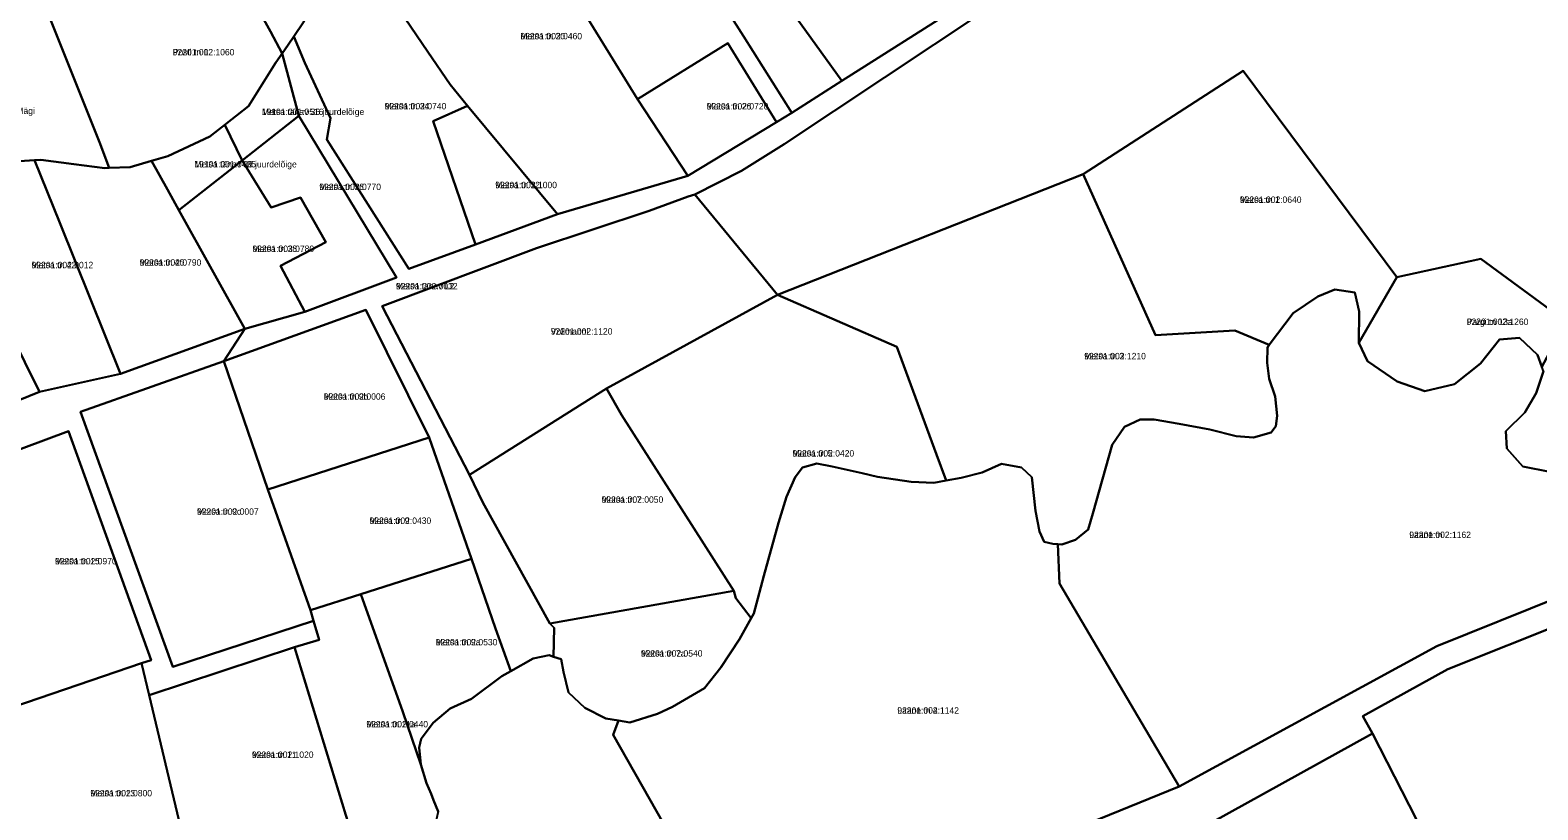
# Model space of a CAD drawing. Extents: x 601493 to 643081, y 6584980 to 6634019.
# Drawn here: x 610753.7 to 611108.4, y 6605638.6 to 6605821.9 of the extents above; entities that cross this region are included whole.
import ezdxf

# ---------------------------------------------------------------- set-up
doc = ezdxf.new("R2010")
doc.units = 0
for name, color, linetype in [('L_AADRESS', 7, 'Continuous'), ('PIIR', 7, 'Continuous'), ('TUNNUS', 7, 'Continuous')]:
    doc.layers.add(name, color=color, linetype=linetype)

msp = doc.modelspace()

# ---------------------------------------------------------------- linework, layer by layer
at = {"layer": 'PIIR'}
for points in [[(611039.07, 6605812.36), (611001.4, 6605788.06), (610929.47, 6605759.72), (610910.09, 6605783.32), (610921.07, 6605788.83), (610931.04, 6605795.1), (611013.55, 6605849.98), (611082.29, 6605891.66), (611115.81, 6605912.81), (611137.5, 6605923.67), (611147.96, 6605926.34), (611157.22, 6605925.86), (611165.66, 6605923.69), (611197.19, 6605914.12), (611207.12, 6605912.54), (611210.66, 6605912.84), (611218.77, 6605915.13), (611225.45, 6605916.03), (611183.62, 6605885.37), (611170.92, 6605860.77), (611135.45, 6605791.96), (611115.08, 6605753.45), (611094.98, 6605768.18), (611075.19, 6605763.83)], [(610941.42, 6605865.54), (610957.04, 6605871.76), (610972.65, 6605827.71), (610944.64, 6605810.06), (610916.52, 6605849.17)], [(610852.47, 6605809.13), (610847.26, 6605816.83), (610834.07, 6605836.28), (610829.65, 6605842.78), (610833.29, 6605846.64), (610838.14, 6605850.04), (610841.61, 6605851.14), (610846.82, 6605852.96), (610850.54, 6605853.06), (610853.73, 6605853.27), (610858.17, 6605855.64), (610860.33, 6605858.94), (610860.54, 6605864.2), (610862.06, 6605861.72), (610880.44, 6605831.95), (610896.61, 6605805.75), (610908.41, 6605787.66), (610877.74, 6605778.64), (610856.61, 6605804.18)], [(610906.04, 6605844.85), (610916.52, 6605849.17), (610944.64, 6605810.06), (610932.85, 6605802.49), (610921.49, 6605820.55)], [(610880.44, 6605831.95), (610906.04, 6605844.85), (610921.49, 6605820.55), (610932.85, 6605802.49), (610929.31, 6605800.33), (610917.86, 6605818.92), (610896.61, 6605805.75)], [(610786.04, 6605792.32), (610782.27, 6605791.18), (610777.19, 6605789.71), (610772.28, 6605789.54), (610770.02, 6605795.62), (610757, 6605828.16), (610795.19, 6605842.52), (610798.67, 6605842.44), (610810.22, 6605821.63), (610812.94, 6605816.49), (610811.52, 6605814.37), (610805.02, 6605804.07), (610795.94, 6605796.95)], [(610824.35, 6605801.23), (610818.27, 6605814.29), (610815.71, 6605820.49), (610818.02, 6605823.86), (610818.43, 6605824.64), (610823.18, 6605833.34), (610828.44, 6605841.49), (610829.65, 6605842.78), (610834.07, 6605836.28), (610847.26, 6605816.83), (610852.47, 6605809.13), (610856.61, 6605804.18), (610848.49, 6605800.56), (610858.47, 6605771.54), (610842.8, 6605765.82), (610823.49, 6605796.26)], [(610724.08, 6605776.33), (610716.89, 6605787.82), (610700.61, 6605813.84), (610757, 6605828.16), (610770.02, 6605795.62), (610772.28, 6605789.54), (610771.22, 6605789.5), (610763.94, 6605790.43), (610756.17, 6605791.47), (610754.72, 6605791.37), (610748.92, 6605790.98), (610744.19, 6605788.8), (610738.01, 6605784.38), (610736.06, 6605782.98), (610733.11, 6605781.31), (610725.97, 6605777.27)], [(610799.46, 6605799.71), (610805.02, 6605804.07), (610811.52, 6605814.37), (610812.94, 6605816.49), (610816.92, 6605801.81), (610803.58, 6605791.27)], [(610896.61, 6605805.75), (610917.86, 6605818.92), (610929.31, 6605800.33), (610908.41, 6605787.66)], [(611018.44, 6605750.22), (611001.4, 6605788.06), (611039.07, 6605812.36), (611075.19, 6605763.83), (611066.24, 6605748.39), (611066.35, 6605755.81), (611065.32, 6605760.25), (611060.61, 6605760.95), (611056.59, 6605759.31), (611050.84, 6605755.35), (611045.21, 6605747.91), (611037.07, 6605751.32)], [(610818.32, 6605755.72), (610812.62, 6605766.52), (610823.28, 6605772.11), (610817.31, 6605782.55), (610810.4, 6605780.24), (610803.58, 6605791.27), (610816.92, 6605801.81), (610839.86, 6605763.75)], [(610848.49, 6605800.56), (610856.61, 6605804.18), (610877.74, 6605778.64), (610858.47, 6605771.54)], [(610795.94, 6605796.95), (610799.46, 6605799.71), (610803.58, 6605791.27), (610788.7, 6605779.61), (610785.99, 6605784.48), (610782.27, 6605791.18), (610786.04, 6605792.32)], [(610755.86, 6605736.89), (610745.42, 6605757.82), (610735.74, 6605776.32), (610733.11, 6605781.31), (610736.06, 6605782.98), (610738.01, 6605784.38), (610744.19, 6605788.8), (610748.92, 6605790.98), (610754.72, 6605791.37), (610760.65, 6605776.64), (610774.92, 6605741.12)], [(610782.27, 6605791.18), (610785.99, 6605784.48), (610788.7, 6605779.61), (610804.19, 6605751.7), (610774.92, 6605741.12), (610760.65, 6605776.64), (610754.72, 6605791.37), (610756.17, 6605791.47), (610763.94, 6605790.43), (610771.22, 6605789.5), (610772.28, 6605789.54), (610777.19, 6605789.71)], [(610788.7, 6605779.61), (610803.58, 6605791.27), (610810.4, 6605780.24), (610817.31, 6605782.55), (610823.28, 6605772.11), (610812.62, 6605766.52), (610818.32, 6605755.72), (610804.19, 6605751.7)], [(610929.47, 6605759.72), (611001.4, 6605788.06), (611018.44, 6605750.22), (611037.07, 6605751.32), (611045.21, 6605747.91), (611044.79, 6605747.34), (611044.67, 6605743.7), (611045.15, 6605739.94), (611046.6, 6605735.82), (611047.09, 6605731.21), (611046.72, 6605728.78), (611045.63, 6605727.33), (611041.51, 6605726.11), (611037.38, 6605726.48), (611031.2, 6605728.05), (611024.04, 6605729.39), (611018.1, 6605730.36), (611014.82, 6605730.36), (611011.18, 6605728.66), (611008.27, 6605724.42), (611003.66, 6605708.29), (611002.56, 6605704.52), (610999.65, 6605702.1), (610996.38, 6605701.01), (610995.48, 6605701.06), (610994.31, 6605701.13), (610992.25, 6605701.61), (610991.16, 6605704.04), (610990.19, 6605708.89), (610989.31, 6605716.83), (610986.95, 6605719.1), (610982.24, 6605719.92), (610977.65, 6605717.9), (610972.75, 6605716.65), (610969.15, 6605716.02), (610966.91, 6605722.11), (610957.55, 6605747.49)], [(610836.52, 6605757.05), (610872.83, 6605770.69), (610899.35, 6605779.45), (610908.48, 6605782.86), (610910.09, 6605783.32), (610929.47, 6605759.72), (610889.25, 6605737.69), (610857.04, 6605717.37)], [(611066.24, 6605748.39), (611075.19, 6605763.83), (611094.98, 6605768.18), (611115.08, 6605753.45), (611109.3, 6605742.79), (611108.3, 6605745.6), (611104.08, 6605749.62), (611099.34, 6605749.21), (611094.9, 6605743.54), (611088.81, 6605738.7), (611081.8, 6605737.05), (611075.31, 6605739.32), (611068.3, 6605744.06)], [(610923.33, 6605683.63), (610919.74, 6605688.32), (610919.22, 6605690.1), (610892.78, 6605731.44), (610889.25, 6605737.69), (610929.47, 6605759.72), (610957.55, 6605747.49), (610966.91, 6605722.11), (610969.15, 6605716.02), (610966.3, 6605715.51), (610960.96, 6605715.69), (610953.07, 6605716.9), (610949.46, 6605717.72), (610942.4, 6605719.33), (610938.76, 6605720.06), (610935.36, 6605719.09), (610933.66, 6605716.78), (610931.6, 6605712.17), (610929.78, 6605706.11), (610926.26, 6605693.62), (610924.86, 6605688.26), (610923.95, 6605684.76)], [(610727.39, 6605736.88), (610724.37, 6605743.01), (610745.42, 6605757.82), (610755.86, 6605736.89), (610731.89, 6605727.19)], [(610799.25, 6605744.13), (610832.65, 6605756.16), (610847.58, 6605726.13), (610809.6, 6605713.9)], [(611137.98, 6605724.9), (611134.69, 6605723.74), (611123.34, 6605720.54), (611111.18, 6605718.07), (611104.89, 6605719.31), (611101.07, 6605723.54), (611100.87, 6605727.66), (611105.31, 6605731.99), (611107.99, 6605736.53), (611109.68, 6605741.73), (611109.3, 6605742.79), (611115.08, 6605753.45)], [(610765.52, 6605732.16), (610799.25, 6605744.13), (610809.6, 6605713.9), (610819.62, 6605685.54), (610820.36, 6605683.04), (610787.23, 6605672.18)], [(610860.2, 6605710.83), (610857.04, 6605717.37), (610889.25, 6605737.69), (610892.78, 6605731.44), (610919.22, 6605690.1), (610875.96, 6605682.43)], [(610736.92, 6605690.82), (610741.9, 6605692.35), (610736.99, 6605718.1), (610762.69, 6605727.65), (610782.16, 6605673.79), (610779.86, 6605673.07), (610743.83, 6605660.73)], [(610857.49, 6605697.63), (610831.47, 6605689.31), (610819.62, 6605685.54), (610809.6, 6605713.9), (610847.58, 6605726.13)], [(610969.15, 6605716.02), (610972.75, 6605716.65), (610977.65, 6605717.9), (610982.24, 6605719.92), (610986.95, 6605719.1), (610989.31, 6605716.83), (610990.19, 6605708.89), (610991.16, 6605704.04), (610992.25, 6605701.61), (610994.31, 6605701.13), (610995.48, 6605701.06), (610995.89, 6605691.84), (611024.03, 6605644.08), (610921.45, 6605602.34), (610890.82, 6605656.18), (610892.13, 6605659.57), (610894.77, 6605659.14), (610901.27, 6605661.11), (610904.78, 6605662.8), (610910.45, 6605666.09), (610912.31, 6605667.17), (610916.19, 6605672.02), (610920.56, 6605678.69), (610923.33, 6605683.63), (610923.95, 6605684.76), (610924.86, 6605688.26), (610926.26, 6605693.62), (610929.78, 6605706.11), (610931.6, 6605712.17), (610933.66, 6605716.78), (610935.36, 6605719.09), (610938.76, 6605720.06), (610942.4, 6605719.33), (610949.46, 6605717.72), (610953.07, 6605716.9), (610960.96, 6605715.69), (610966.3, 6605715.51)], [(610857.55, 6605664.71), (610852.46, 6605662.43), (610848.49, 6605659.05), (610845.7, 6605655.29), (610845.22, 6605653.23), (610845.58, 6605649.22), (610841.35, 6605661.65), (610831.47, 6605689.31), (610857.49, 6605697.63), (610863.13, 6605681.2), (610866.74, 6605671.16), (610864.67, 6605669.97)], [(610827.98, 6605637.29), (610815.87, 6605676.82), (610821.71, 6605678.56), (610820.37, 6605683.04), (610819.62, 6605685.54), (610831.47, 6605689.31), (610841.35, 6605661.65), (610845.58, 6605649.22), (610846.92, 6605644.86), (610847.99, 6605642.32), (610848.61, 6605640.85), (610849.7, 6605638.18), (610848.85, 6605634.42), (610846.91, 6605632.73), (610844.24, 6605630.91), (610839.88, 6605629.75), (610835.85, 6605629.92), (610830.05, 6605630.64)], [(610910.45, 6605666.09), (610904.78, 6605662.8), (610901.27, 6605661.11), (610894.77, 6605659.14), (610892.13, 6605659.57), (610889.09, 6605660.07), (610884.15, 6605662.54), (610880.33, 6605666.15), (610879.2, 6605671), (610878.59, 6605673.99), (610876.83, 6605674.57), (610876.97, 6605681.39), (610875.96, 6605682.43), (610919.22, 6605690.1), (610919.74, 6605688.32), (610923.33, 6605683.63), (610920.56, 6605678.69), (610916.19, 6605672.02), (610912.31, 6605667.17)], [(611088.53, 6605619.27), (611069.45, 6605656.52), (611067.2, 6605660.57), (611087.22, 6605671.62), (611115.5, 6605682.98), (611151.71, 6605688.75), (611168.49, 6605687.07), (611218.29, 6605624.68), (611110.62, 6605574.97)], [(610781.67, 6605665.57), (610815.87, 6605676.82), (610827.98, 6605637.29), (610830.05, 6605630.64), (610826.46, 6605631.07), (610821.35, 6605632.06), (610817.81, 6605633.21), (610814.35, 6605634.61), (610812.2, 6605633.94), (610808.01, 6605630.33), (610803.9, 6605625.96), (610800.93, 6605623.58), (610797.06, 6605621.93), (610794.99, 6605622.18), (610792.88, 6605622.67), (610791.88, 6605622.82), (610789.07, 6605634.6)], [(610743.83, 6605660.73), (610779.86, 6605673.07), (610781.67, 6605665.57), (610789.07, 6605634.6), (610791.88, 6605622.82), (610789.57, 6605623.17), (610786.44, 6605623.82), (610782.81, 6605623.91), (610778.86, 6605623.49), (610776.31, 6605622.06), (610773.28, 6605620), (610769.64, 6605616.96), (610766.36, 6605612.48), (610765.03, 6605609.57), (610764.18, 6605605.32), (610762.84, 6605598.77), (610762.72, 6605591), (610762.35, 6605585.3), (610761.75, 6605580.09), (610758.89, 6605592.68)], [(611069.45, 6605656.52), (611088.53, 6605619.27), (611082.6, 6605616.38), (611063.53, 6605606.97), (611049.4, 6605600.24), (611040.82, 6605621.98), (611031.37, 6605635.42)]]:
    msp.add_lwpolyline(points, close=True, dxfattribs=at)
for points in [[(611013.55, 6605849.98), (610931.04, 6605795.1), (610921.07, 6605788.83), (610910.09, 6605783.32), (610908.48, 6605782.86), (610899.35, 6605779.45), (610872.83, 6605770.69), (610836.52, 6605757.05), (610857.04, 6605717.37), (610860.2, 6605710.83), (610875.96, 6605682.43), (610876.97, 6605681.39), (610876.83, 6605674.57), (610875.8, 6605674.91), (610871.99, 6605674.19), (610866.74, 6605671.16), (610863.13, 6605681.2), (610857.49, 6605697.63), (610847.58, 6605726.13), (610832.65, 6605756.16), (610799.25, 6605744.13), (610804.19, 6605751.7), (610818.32, 6605755.72), (610839.86, 6605763.75), (610816.92, 6605801.81), (610812.94, 6605816.49), (610814.36, 6605818.52), (610815.71, 6605820.49), (610818.27, 6605814.29), (610824.35, 6605801.23), (610823.49, 6605796.26), (610842.8, 6605765.82), (610858.47, 6605771.54), (610877.74, 6605778.64), (610908.41, 6605787.66), (610929.31, 6605800.33), (610932.85, 6605802.49), (610944.64, 6605810.06), (610972.65, 6605827.71)], [(610818.02, 6605823.86), (610815.71, 6605820.49), (610814.36, 6605818.52), (610812.94, 6605816.49), (610810.22, 6605821.63), (610798.67, 6605842.44)], [(611113.89, 6605688.79), (611084.63, 6605677.04), (611024.03, 6605644.08), (610995.89, 6605691.84), (610995.48, 6605701.06), (610996.38, 6605701.01), (610999.65, 6605702.1), (611002.56, 6605704.52), (611003.66, 6605708.29), (611008.27, 6605724.42), (611011.18, 6605728.66), (611014.82, 6605730.36), (611018.1, 6605730.36), (611024.04, 6605729.39), (611031.2, 6605728.05), (611037.38, 6605726.48), (611041.51, 6605726.11), (611045.63, 6605727.33), (611046.72, 6605728.78), (611047.09, 6605731.21), (611046.6, 6605735.82), (611045.15, 6605739.94), (611044.67, 6605743.7), (611044.79, 6605747.34), (611045.21, 6605747.91), (611050.84, 6605755.35), (611056.59, 6605759.31), (611060.61, 6605760.95), (611065.32, 6605760.25), (611066.35, 6605755.81), (611066.24, 6605748.39), (611068.3, 6605744.06), (611075.31, 6605739.32), (611081.8, 6605737.05), (611088.81, 6605738.7), (611094.9, 6605743.54), (611099.34, 6605749.21), (611104.08, 6605749.62), (611108.3, 6605745.6), (611109.3, 6605742.79)], [(610731.89, 6605727.19), (610755.86, 6605736.89), (610774.92, 6605741.12), (610804.19, 6605751.7), (610799.25, 6605744.13), (610765.52, 6605732.16), (610787.23, 6605672.18), (610820.36, 6605683.04), (610821.71, 6605678.56), (610815.87, 6605676.82), (610781.67, 6605665.57), (610779.86, 6605673.07), (610782.16, 6605673.79), (610762.69, 6605727.65), (610736.99, 6605718.1)], [(611109.68, 6605741.73), (611107.99, 6605736.53), (611105.31, 6605731.99), (611100.87, 6605727.66), (611101.07, 6605723.54), (611104.89, 6605719.31), (611111.18, 6605718.07)], [(611115.5, 6605682.98), (611087.22, 6605671.62), (611067.2, 6605660.57), (611069.45, 6605656.52), (611031.37, 6605635.42), (611028.56, 6605633.82), (611024.47, 6605631.55), (610995.36, 6605620.2), (610966.05, 6605608.81), (610938.08, 6605597.9), (610908.61, 6605588.8), (610885.09, 6605581.43), (610860.63, 6605573.77), (610840.79, 6605567.48), (610821.51, 6605561.58), (610813.07, 6605558.78), (610790.01, 6605551.49), (610786.38, 6605560.85), (610850.15, 6605580.93), (610921.45, 6605602.34), (611024.03, 6605644.08), (611084.63, 6605677.04), (611113.89, 6605688.79)], [(610849.7, 6605638.18), (610848.61, 6605640.85), (610847.99, 6605642.32), (610846.92, 6605644.86), (610845.58, 6605649.22), (610845.22, 6605653.23), (610845.7, 6605655.29), (610848.49, 6605659.05), (610852.46, 6605662.43), (610857.55, 6605664.71), (610864.67, 6605669.97), (610866.74, 6605671.16), (610871.99, 6605674.19), (610875.8, 6605674.91), (610876.83, 6605674.57), (610878.59, 6605673.99), (610879.2, 6605671), (610880.33, 6605666.15), (610884.15, 6605662.54), (610889.09, 6605660.07), (610892.13, 6605659.57), (610890.82, 6605656.18), (610921.45, 6605602.34)]]:
    msp.add_lwpolyline(points, dxfattribs=at)

# ---------------------------------------------------------------- texts
at = {"layer": 'L_AADRESS'}
for s, p in [('Metsa tn 30', (610869.03, 6605819.8)), ('Posti tn 12', (610787.24, 6605816.03)), ('Posti tn 12a // Mägi', (610737.62, 6605802.24)), ('Metsa tänav 36 juurdelõige', (610808.19, 6605802)), ('Metsa tn 34', (610837.09, 6605803.32)), ('Metsa tn 26', (610912.85, 6605803.29)), ('Metsa tänav 38 juurdelõige', (610792.32, 6605789.66)), ('Metsa tn 36', (610821.72, 6605784.34)), ('Metsa tn 32', (610863.12, 6605784.78)), ('Metsa tn 1', (611038.29, 6605781.33)), ('Metsa tn 38', (610805.99, 6605769.79)), ('Metsa tn 42', (610754.02, 6605765.96)), ('Metsa tn 40', (610779.45, 6605766.56)), ('Metsa tänav L2', (610839.75, 6605760.99)), ('Vollmanni', (610876.17, 6605750.35)), ('Pargi tn 13a', (611091.66, 6605752.62)), ('Metsa tn 3', (611001.67, 6605744.54)), ('Metsa tn 9b', (610822.76, 6605735.03)), ('Metsa tn 5', (610933.05, 6605721.67)), ('Metsa tn 9c', (610792.94, 6605707.97)), ('Metsa tn 7', (610888.13, 6605710.79)), ('Metsa tn 9', (610833.54, 6605705.83)), ('Lääne tn 2', (611078.15, 6605702.51)), ('Metsa tn 15', (610759.54, 6605696.3)), ('Metsa tn 9a', (610849.11, 6605677.26)), ('Metsa tn 7a', (610897.36, 6605674.62)), ('Lääne tn 4', (610957.7, 6605661.2)), ('Metsa tn 11a', (610832.79, 6605657.96)), ('Metsa tn 11', (610805.86, 6605650.79)), ('Metsa tn 13', (610767.86, 6605641.74))]:
    msp.add_text(s, height=1.5, dxfattribs=at).set_placement(p)
at = {"layer": 'TUNNUS'}
for s, p in [('92201:002:0460', (610869.03, 6605819.8)), ('92201:002:1060', (610787.24, 6605816.03)), ('19101:001:0516', (610808.19, 6605802)), ('92201:002:0740', (610837.09, 6605803.32)), ('92201:002:0720', (610912.85, 6605803.29)), ('19101:001:0485', (610792.32, 6605789.66)), ('92201:002:0770', (610821.72, 6605784.34)), ('92201:002:1000', (610863.12, 6605784.78)), ('92201:002:0640', (611038.29, 6605781.33)), ('92201:002:0780', (610805.99, 6605769.79)), ('92201:002:0012', (610754.02, 6605765.96)), ('92201:002:0790', (610779.45, 6605766.56)), ('92201:002:0032', (610839.75, 6605760.99)), ('92201:002:1120', (610876.17, 6605750.35)), ('92201:002:1260', (611091.66, 6605752.62)), ('92201:002:1210', (611001.67, 6605744.54)), ('92201:002:0006', (610822.76, 6605735.03)), ('92201:002:0420', (610933.05, 6605721.67)), ('92201:002:0007', (610792.94, 6605707.97)), ('92201:002:0050', (610888.13, 6605710.79)), ('92201:002:0430', (610833.54, 6605705.83)), ('92201:002:1162', (611078.15, 6605702.51)), ('92201:002:0970', (610759.54, 6605696.3)), ('92201:002:0530', (610849.11, 6605677.26)), ('92201:002:0540', (610897.36, 6605674.62)), ('92201:002:1142', (610957.7, 6605661.2)), ('92201:002:0440', (610832.79, 6605657.96)), ('92201:002:1020', (610805.86, 6605650.79)), ('92201:002:0800', (610767.86, 6605641.74))]:
    msp.add_text(s, height=1.5, dxfattribs=at).set_placement(p)

doc.saveas('drawing.dxf')
